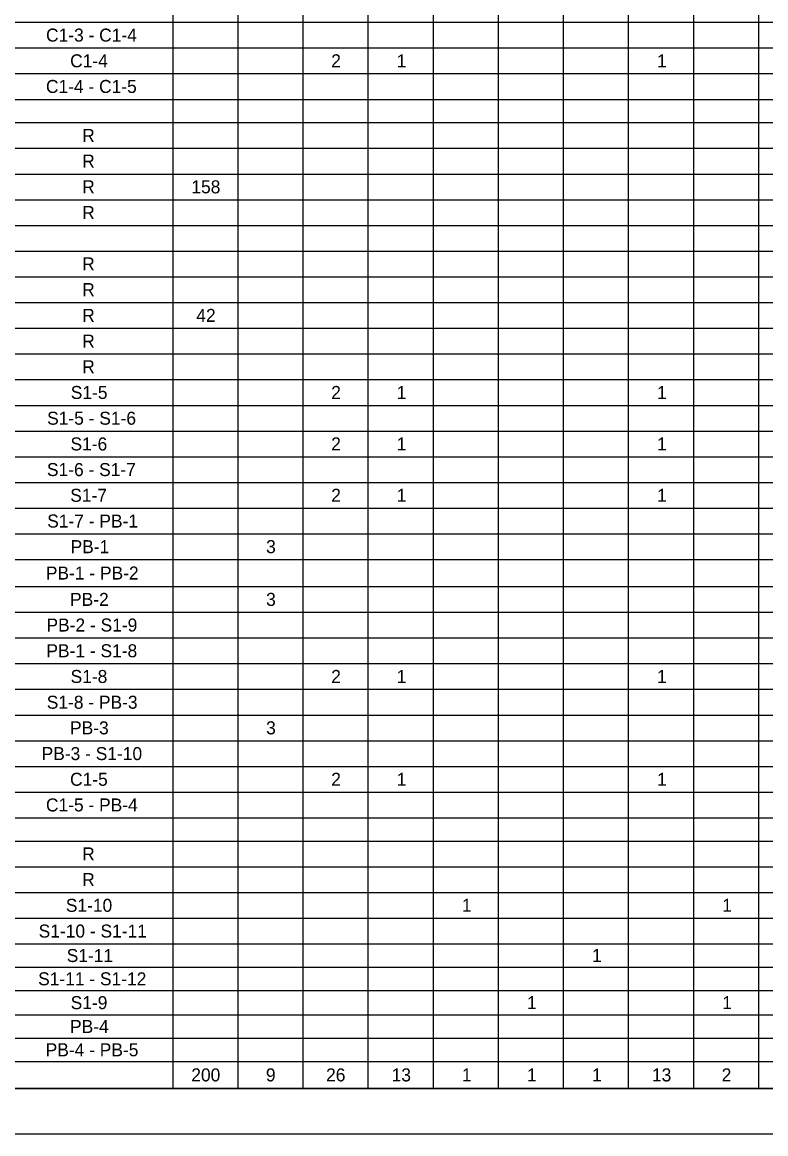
# Model space of a CAD drawing. Extents: x -1022.2 to -988.2, y -965.8 to -943.8.
# Drawn here: x -1013.62 to -1005.35, y -965.79 to -953.43 of the extents above; entities that cross this region are included whole.
import ezdxf

# ---------------------------------------------------------------- set-up
doc = ezdxf.new("R2010")
doc.units = 0
for name, color, linetype in [('Default', 7, 'Continuous'), ('SH_Border', 7, 'Continuous'), ('SH_Cut_Line', 7, 'Continuous')]:
    doc.layers.add(name, color=color, linetype=linetype)

msp = doc.modelspace()

# ---------------------------------------------------------------- linework, layer by layer
at = {"layer": 'Default'}
for p, q in [((-1011.942, -952.573), (-1011.942, -953.43)), ((-1011.218, -952.573), (-1011.218, -953.43)), ((-1010.494, -952.573), (-1010.494, -953.43)), ((-1009.771, -952.573), (-1009.771, -953.43)), ((-1009.047, -952.573), (-1009.047, -953.43)), ((-1008.323, -952.573), (-1008.323, -953.43)), ((-1007.6, -952.573), (-1007.6, -953.43)), ((-1006.876, -952.573), (-1006.876, -953.43)), ((-1006.152, -952.573), (-1006.152, -953.43)), ((-1005.428, -952.573), (-1005.428, -953.43)), ((-1016.817, -953.43), (-1009.047, -953.43)), ((-1011.942, -953.43), (-1011.942, -954.001)), ((-1011.218, -953.43), (-1011.218, -954.001)), ((-1010.494, -953.43), (-1010.494, -954.001)), ((-1009.771, -953.43), (-1009.771, -954.001)), ((-1009.047, -953.43), (-1008.323, -953.43)), ((-1009.047, -953.43), (-1009.047, -954.001)), ((-1008.323, -953.43), (-1007.6, -953.43)), ((-1008.323, -953.43), (-1008.323, -954.001)), ((-1007.6, -953.43), (-1006.876, -953.43)), ((-1007.6, -953.43), (-1007.6, -954.001)), ((-1006.876, -953.43), (-1005.428, -953.43)), ((-1006.876, -953.43), (-1006.876, -954.001)), ((-1006.152, -953.43), (-1006.152, -954.001)), ((-1005.428, -953.43), (-998.915, -953.43)), ((-1005.428, -953.43), (-1005.428, -954.001)), ((-1016.817, -953.716), (-1009.047, -953.716)), ((-1009.047, -953.716), (-1008.323, -953.716)), ((-1008.323, -953.716), (-1007.6, -953.716)), ((-1007.6, -953.716), (-1006.876, -953.716)), ((-1006.876, -953.716), (-1005.428, -953.716)), ((-1005.428, -953.716), (-998.915, -953.716)), ((-1016.817, -954.001), (-1009.047, -954.001)), ((-1011.942, -954.001), (-1011.942, -955.403)), ((-1011.218, -954.001), (-1011.218, -955.403)), ((-1010.494, -954.001), (-1010.494, -955.403)), ((-1009.771, -954.001), (-1009.771, -955.403)), ((-1009.047, -954.001), (-1008.323, -954.001)), ((-1009.047, -954.001), (-1009.047, -955.403)), ((-1008.323, -954.001), (-1007.6, -954.001)), ((-1008.323, -954.001), (-1008.323, -955.403)), ((-1007.6, -954.001), (-1006.876, -954.001)), ((-1007.6, -954.001), (-1007.6, -955.403)), ((-1006.876, -954.001), (-1005.428, -954.001)), ((-1006.876, -954.001), (-1006.876, -955.403)), ((-1006.152, -954.001), (-1006.152, -955.403)), ((-1005.428, -954.001), (-998.915, -954.001)), ((-1005.428, -954.001), (-1005.428, -955.403)), ((-1016.817, -954.287), (-1009.047, -954.287)), ((-1009.047, -954.287), (-1008.323, -954.287)), ((-1008.323, -954.287), (-1007.6, -954.287)), ((-1007.6, -954.287), (-1006.876, -954.287)), ((-1006.876, -954.287), (-1005.428, -954.287)), ((-1005.428, -954.287), (-998.915, -954.287)), ((-1016.817, -954.546), (-1009.047, -954.546)), ((-1009.047, -954.546), (-1008.323, -954.546)), ((-1008.323, -954.546), (-1007.6, -954.546)), ((-1007.6, -954.546), (-1006.876, -954.546)), ((-1006.876, -954.546), (-1005.428, -954.546)), ((-1005.428, -954.546), (-998.915, -954.546)), ((-1016.817, -954.831), (-1009.047, -954.831)), ((-1009.047, -954.831), (-1008.323, -954.831)), ((-1008.323, -954.831), (-1007.6, -954.831)), ((-1007.6, -954.831), (-1006.876, -954.831)), ((-1006.876, -954.831), (-1005.428, -954.831)), ((-1005.428, -954.831), (-998.915, -954.831)), ((-1016.817, -955.117), (-1009.047, -955.117)), ((-1009.047, -955.117), (-1008.323, -955.117)), ((-1008.323, -955.117), (-1007.6, -955.117)), ((-1007.6, -955.117), (-1006.876, -955.117)), ((-1006.876, -955.117), (-1005.428, -955.117)), ((-1005.428, -955.117), (-998.915, -955.117)), ((-1016.817, -955.403), (-1009.047, -955.403)), ((-1011.942, -955.403), (-1011.942, -955.974)), ((-1011.218, -955.403), (-1011.218, -955.974)), ((-1010.494, -955.403), (-1010.494, -955.974)), ((-1009.771, -955.403), (-1009.771, -955.974)), ((-1009.047, -955.403), (-1008.323, -955.403)), ((-1009.047, -955.403), (-1009.047, -955.974)), ((-1008.323, -955.403), (-1007.6, -955.403)), ((-1008.323, -955.403), (-1008.323, -955.974)), ((-1007.6, -955.403), (-1006.876, -955.403)), ((-1007.6, -955.403), (-1007.6, -955.974)), ((-1006.876, -955.403), (-1005.428, -955.403)), ((-1006.876, -955.403), (-1006.876, -955.974)), ((-1006.152, -955.403), (-1006.152, -955.974)), ((-1005.428, -955.403), (-998.915, -955.403)), ((-1005.428, -955.403), (-1005.428, -955.974)), ((-1016.817, -955.688), (-1009.047, -955.688)), ((-1009.047, -955.688), (-1008.323, -955.688)), ((-1008.323, -955.688), (-1007.6, -955.688)), ((-1007.6, -955.688), (-1006.876, -955.688)), ((-1006.876, -955.688), (-1005.428, -955.688)), ((-1005.428, -955.688), (-998.915, -955.688)), ((-1016.817, -955.974), (-1009.047, -955.974)), ((-1011.942, -955.974), (-1011.942, -956.831)), ((-1011.218, -955.974), (-1011.218, -956.831)), ((-1010.494, -955.974), (-1010.494, -956.831)), ((-1009.771, -955.974), (-1009.771, -956.831)), ((-1009.047, -955.974), (-1008.323, -955.974)), ((-1009.047, -955.974), (-1009.047, -956.831)), ((-1008.323, -955.974), (-1007.6, -955.974)), ((-1008.323, -955.974), (-1008.323, -956.831)), ((-1007.6, -955.974), (-1006.876, -955.974)), ((-1007.6, -955.974), (-1007.6, -956.831)), ((-1006.876, -955.974), (-1005.428, -955.974)), ((-1006.876, -955.974), (-1006.876, -956.831)), ((-1006.152, -955.974), (-1006.152, -956.831)), ((-1005.428, -955.974), (-998.915, -955.974)), ((-1005.428, -955.974), (-1005.428, -956.831)), ((-1016.817, -956.26), (-1009.047, -956.26)), ((-1009.047, -956.26), (-1008.323, -956.26)), ((-1008.323, -956.26), (-1007.6, -956.26)), ((-1007.6, -956.26), (-1006.876, -956.26)), ((-1006.876, -956.26), (-1005.428, -956.26)), ((-1005.428, -956.26), (-998.915, -956.26)), ((-1016.817, -956.546), (-1009.047, -956.546)), ((-1009.047, -956.546), (-1008.323, -956.546)), ((-1008.323, -956.546), (-1007.6, -956.546)), ((-1007.6, -956.546), (-1006.876, -956.546)), ((-1006.876, -956.546), (-1005.428, -956.546)), ((-1005.428, -956.546), (-998.915, -956.546)), ((-1016.817, -956.831), (-1009.047, -956.831)), ((-1011.942, -956.831), (-1011.942, -957.403)), ((-1011.218, -956.831), (-1011.218, -957.403)), ((-1010.494, -956.831), (-1010.494, -957.403)), ((-1009.771, -956.831), (-1009.771, -957.403)), ((-1009.047, -956.831), (-1008.323, -956.831)), ((-1009.047, -956.831), (-1009.047, -957.403)), ((-1008.323, -956.831), (-1007.6, -956.831)), ((-1008.323, -956.831), (-1008.323, -957.403)), ((-1007.6, -956.831), (-1006.876, -956.831)), ((-1007.6, -956.831), (-1007.6, -957.403)), ((-1006.876, -956.831), (-1005.428, -956.831)), ((-1006.876, -956.831), (-1006.876, -957.403)), ((-1006.152, -956.831), (-1006.152, -957.403)), ((-1005.428, -956.831), (-998.915, -956.831)), ((-1005.428, -956.831), (-1005.428, -957.403)), ((-1016.817, -957.117), (-1009.047, -957.117)), ((-1009.047, -957.117), (-1008.323, -957.117)), ((-1008.323, -957.117), (-1007.6, -957.117)), ((-1007.6, -957.117), (-1006.876, -957.117)), ((-1006.876, -957.117), (-1005.428, -957.117)), ((-1005.428, -957.117), (-998.915, -957.117)), ((-1016.817, -957.403), (-1009.047, -957.403)), ((-1011.942, -957.403), (-1011.942, -958.26)), ((-1011.218, -957.403), (-1011.218, -958.26)), ((-1010.494, -957.403), (-1010.494, -958.26)), ((-1009.771, -957.403), (-1009.771, -958.26)), ((-1009.047, -957.403), (-1008.323, -957.403)), ((-1009.047, -957.403), (-1009.047, -958.26)), ((-1008.323, -957.403), (-1007.6, -957.403)), ((-1008.323, -957.403), (-1008.323, -958.26)), ((-1007.6, -957.403), (-1006.876, -957.403)), ((-1007.6, -957.403), (-1007.6, -958.26)), ((-1006.876, -957.403), (-1005.428, -957.403)), ((-1006.876, -957.403), (-1006.876, -958.26)), ((-1006.152, -957.403), (-1006.152, -958.26)), ((-1005.428, -957.403), (-998.915, -957.403)), ((-1005.428, -957.403), (-1005.428, -958.26)), ((-1016.817, -957.689), (-1009.047, -957.689)), ((-1009.047, -957.689), (-1008.323, -957.689)), ((-1008.323, -957.689), (-1007.6, -957.689)), ((-1007.6, -957.689), (-1006.876, -957.689)), ((-1006.876, -957.689), (-1005.428, -957.689)), ((-1005.428, -957.689), (-998.915, -957.689)), ((-1016.817, -957.974), (-1009.047, -957.974)), ((-1009.047, -957.974), (-1008.323, -957.974)), ((-1008.323, -957.974), (-1007.6, -957.974)), ((-1007.6, -957.974), (-1006.876, -957.974)), ((-1006.876, -957.974), (-1005.428, -957.974)), ((-1005.428, -957.974), (-998.915, -957.974)), ((-1016.817, -958.26), (-1009.047, -958.26)), ((-1011.942, -958.26), (-1011.942, -958.832)), ((-1011.218, -958.26), (-1011.218, -958.832)), ((-1010.494, -958.26), (-1010.494, -958.832)), ((-1009.771, -958.26), (-1009.771, -958.832)), ((-1009.047, -958.26), (-1008.323, -958.26)), ((-1009.047, -958.26), (-1009.047, -958.832)), ((-1008.323, -958.26), (-1007.6, -958.26)), ((-1008.323, -958.26), (-1008.323, -958.832)), ((-1007.6, -958.26), (-1006.876, -958.26)), ((-1007.6, -958.26), (-1007.6, -958.832)), ((-1006.876, -958.26), (-1005.428, -958.26)), ((-1006.876, -958.26), (-1006.876, -958.832)), ((-1006.152, -958.26), (-1006.152, -958.832)), ((-1005.428, -958.26), (-998.915, -958.26)), ((-1005.428, -958.26), (-1005.428, -958.832)), ((-1016.817, -958.546), (-1009.047, -958.546)), ((-1009.047, -958.546), (-1008.323, -958.546)), ((-1008.323, -958.546), (-1007.6, -958.546)), ((-1007.6, -958.546), (-1006.876, -958.546)), ((-1006.876, -958.546), (-1005.428, -958.546)), ((-1005.428, -958.546), (-998.915, -958.546)), ((-1016.817, -958.832), (-1009.047, -958.832)), ((-1011.942, -958.832), (-1011.942, -959.702)), ((-1011.218, -958.832), (-1011.218, -959.702)), ((-1010.494, -958.832), (-1010.494, -959.702)), ((-1009.771, -958.832), (-1009.771, -959.702)), ((-1009.047, -958.832), (-1008.323, -958.832)), ((-1009.047, -958.832), (-1009.047, -959.702)), ((-1008.323, -958.832), (-1007.6, -958.832)), ((-1008.323, -958.832), (-1008.323, -959.702)), ((-1007.6, -958.832), (-1006.876, -958.832)), ((-1007.6, -958.832), (-1007.6, -959.702)), ((-1006.876, -958.832), (-1005.428, -958.832)), ((-1006.876, -958.832), (-1006.876, -959.702)), ((-1006.152, -958.832), (-1006.152, -959.702)), ((-1005.428, -958.832), (-998.915, -958.832)), ((-1005.428, -958.832), (-1005.428, -959.702)), ((-1016.817, -959.117), (-1009.047, -959.117)), ((-1009.047, -959.117), (-1008.323, -959.117)), ((-1008.323, -959.117), (-1007.6, -959.117)), ((-1007.6, -959.117), (-1006.876, -959.117)), ((-1006.876, -959.117), (-1005.428, -959.117)), ((-1005.428, -959.117), (-998.915, -959.117)), ((-1016.817, -959.403), (-1009.047, -959.403)), ((-1009.047, -959.403), (-1008.323, -959.403)), ((-1008.323, -959.403), (-1007.6, -959.403)), ((-1007.6, -959.403), (-1006.876, -959.403)), ((-1006.876, -959.403), (-1005.428, -959.403)), ((-1005.428, -959.403), (-998.915, -959.403)), ((-1016.817, -959.702), (-1009.047, -959.702)), ((-1011.942, -959.702), (-1011.942, -959.988)), ((-1011.218, -959.702), (-1011.218, -959.988)), ((-1010.494, -959.702), (-1010.494, -959.988)), ((-1009.771, -959.702), (-1009.771, -959.988)), ((-1009.047, -959.702), (-1008.323, -959.702)), ((-1009.047, -959.702), (-1009.047, -959.988)), ((-1008.323, -959.702), (-1007.6, -959.702)), ((-1008.323, -959.702), (-1008.323, -959.988)), ((-1007.6, -959.702), (-1006.876, -959.702)), ((-1007.6, -959.702), (-1007.6, -959.988)), ((-1006.876, -959.702), (-1005.428, -959.702)), ((-1006.876, -959.702), (-1006.876, -959.988)), ((-1006.152, -959.702), (-1006.152, -959.988)), ((-1005.428, -959.702), (-998.915, -959.702)), ((-1005.428, -959.702), (-1005.428, -959.988)), ((-1016.817, -959.988), (-1009.047, -959.988)), ((-1011.942, -959.988), (-1011.942, -965.281)), ((-1011.218, -959.988), (-1011.218, -965.281)), ((-1010.494, -959.988), (-1010.494, -965.281)), ((-1009.771, -959.988), (-1009.771, -965.281)), ((-1009.047, -959.988), (-1008.323, -959.988)), ((-1009.047, -959.988), (-1009.047, -965.281)), ((-1008.323, -959.988), (-1007.6, -959.988)), ((-1008.323, -959.988), (-1008.323, -965.281)), ((-1007.6, -959.988), (-1006.876, -959.988)), ((-1007.6, -959.988), (-1007.6, -965.281)), ((-1006.876, -959.988), (-1005.428, -959.988)), ((-1006.876, -959.988), (-1006.876, -965.281)), ((-1006.152, -959.988), (-1006.152, -965.281)), ((-1005.428, -959.988), (-998.915, -959.988)), ((-1005.428, -959.988), (-1005.428, -965.281)), ((-1016.817, -960.274), (-1009.047, -960.274)), ((-1009.047, -960.274), (-1008.323, -960.274)), ((-1008.323, -960.274), (-1007.6, -960.274)), ((-1007.6, -960.274), (-1006.876, -960.274)), ((-1006.876, -960.274), (-1005.428, -960.274)), ((-1005.428, -960.274), (-998.915, -960.274)), ((-1016.817, -960.56), (-1009.047, -960.56)), ((-1009.047, -960.56), (-1008.323, -960.56)), ((-1008.323, -960.56), (-1007.6, -960.56)), ((-1007.6, -960.56), (-1006.876, -960.56)), ((-1006.876, -960.56), (-1005.428, -960.56)), ((-1005.428, -960.56), (-998.915, -960.56)), ((-1016.817, -960.845), (-1009.047, -960.845)), ((-1009.047, -960.845), (-1008.323, -960.845)), ((-1008.323, -960.845), (-1007.6, -960.845)), ((-1007.6, -960.845), (-1006.876, -960.845)), ((-1006.876, -960.845), (-1005.428, -960.845)), ((-1005.428, -960.845), (-998.915, -960.845)), ((-1016.817, -961.131), (-1009.047, -961.131)), ((-1009.047, -961.131), (-1008.323, -961.131)), ((-1008.323, -961.131), (-1007.6, -961.131)), ((-1007.6, -961.131), (-1006.876, -961.131)), ((-1006.876, -961.131), (-1005.428, -961.131)), ((-1005.428, -961.131), (-998.915, -961.131)), ((-1016.817, -961.417), (-1009.047, -961.417)), ((-1009.047, -961.417), (-1008.323, -961.417)), ((-1008.323, -961.417), (-1007.6, -961.417)), ((-1007.6, -961.417), (-1006.876, -961.417)), ((-1006.876, -961.417), (-1005.428, -961.417)), ((-1005.428, -961.417), (-998.915, -961.417)), ((-1016.817, -961.703), (-1009.047, -961.703)), ((-1009.047, -961.703), (-1008.323, -961.703)), ((-1008.323, -961.703), (-1007.6, -961.703)), ((-1007.6, -961.703), (-1006.876, -961.703)), ((-1006.876, -961.703), (-1005.428, -961.703)), ((-1005.428, -961.703), (-998.915, -961.703)), ((-1016.817, -961.988), (-1009.047, -961.988)), ((-1009.047, -961.988), (-1008.323, -961.988)), ((-1008.323, -961.988), (-1007.6, -961.988)), ((-1007.6, -961.988), (-1006.876, -961.988)), ((-1006.876, -961.988), (-1005.428, -961.988)), ((-1005.428, -961.988), (-998.915, -961.988)), ((-1016.817, -962.274), (-1009.047, -962.274)), ((-1009.047, -962.274), (-1008.323, -962.274)), ((-1008.323, -962.274), (-1007.6, -962.274)), ((-1007.6, -962.274), (-1006.876, -962.274)), ((-1006.876, -962.274), (-1005.428, -962.274)), ((-1005.428, -962.274), (-998.915, -962.274)), ((-1016.817, -962.533), (-1009.047, -962.533)), ((-1009.047, -962.533), (-1008.323, -962.533)), ((-1008.323, -962.533), (-1007.6, -962.533)), ((-1007.6, -962.533), (-1006.876, -962.533)), ((-1006.876, -962.533), (-1005.428, -962.533)), ((-1005.428, -962.533), (-998.915, -962.533)), ((-1016.817, -962.818), (-1009.047, -962.818)), ((-1009.047, -962.818), (-1008.323, -962.818)), ((-1008.323, -962.818), (-1007.6, -962.818)), ((-1007.6, -962.818), (-1006.876, -962.818)), ((-1006.876, -962.818), (-1005.428, -962.818)), ((-1005.428, -962.818), (-998.915, -962.818)), ((-1016.817, -963.104), (-1009.047, -963.104)), ((-1009.047, -963.104), (-1008.323, -963.104)), ((-1008.323, -963.104), (-1007.6, -963.104)), ((-1007.6, -963.104), (-1006.876, -963.104)), ((-1006.876, -963.104), (-1005.428, -963.104)), ((-1005.428, -963.104), (-998.915, -963.104)), ((-1016.817, -963.39), (-1009.047, -963.39)), ((-1009.047, -963.39), (-1008.323, -963.39)), ((-1008.323, -963.39), (-1007.6, -963.39)), ((-1007.6, -963.39), (-1006.876, -963.39)), ((-1006.876, -963.39), (-1005.428, -963.39)), ((-1005.428, -963.39), (-998.915, -963.39)), ((-1016.817, -963.676), (-1009.047, -963.676)), ((-1009.047, -963.676), (-1008.323, -963.676)), ((-1008.323, -963.676), (-1007.6, -963.676)), ((-1007.6, -963.676), (-1006.876, -963.676)), ((-1006.876, -963.676), (-1005.428, -963.676)), ((-1005.428, -963.676), (-998.915, -963.676)), ((-1016.817, -963.934), (-1009.047, -963.934)), ((-1009.047, -963.934), (-1008.323, -963.934)), ((-1008.323, -963.934), (-1007.6, -963.934)), ((-1007.6, -963.934), (-1006.876, -963.934)), ((-1006.876, -963.934), (-1005.428, -963.934)), ((-1005.428, -963.934), (-998.915, -963.934)), ((-1016.817, -964.193), (-1009.047, -964.193)), ((-1009.047, -964.193), (-1008.323, -964.193)), ((-1008.323, -964.193), (-1007.6, -964.193)), ((-1007.6, -964.193), (-1006.876, -964.193)), ((-1006.876, -964.193), (-1005.428, -964.193)), ((-1005.428, -964.193), (-998.915, -964.193)), ((-1016.817, -964.465), (-1009.047, -964.465)), ((-1009.047, -964.465), (-1008.323, -964.465)), ((-1008.323, -964.465), (-1007.6, -964.465)), ((-1007.6, -964.465), (-1006.876, -964.465)), ((-1006.876, -964.465), (-1005.428, -964.465)), ((-1005.428, -964.465), (-998.915, -964.465)), ((-1016.817, -964.723), (-1009.047, -964.723)), ((-1009.047, -964.723), (-1008.323, -964.723)), ((-1008.323, -964.723), (-1007.6, -964.723)), ((-1007.6, -964.723), (-1006.876, -964.723)), ((-1006.876, -964.723), (-1005.428, -964.723)), ((-1005.428, -964.723), (-998.915, -964.723)), ((-1016.817, -964.982), (-1009.047, -964.982)), ((-1009.047, -964.982), (-1008.323, -964.982)), ((-1008.323, -964.982), (-1007.6, -964.982)), ((-1007.6, -964.982), (-1006.876, -964.982)), ((-1006.876, -964.982), (-1005.428, -964.982)), ((-1005.428, -964.982), (-998.915, -964.982)), ((-1016.817, -965.281), (-1009.047, -965.281)), ((-1009.047, -965.281), (-1008.323, -965.281)), ((-1008.323, -965.281), (-1007.6, -965.281)), ((-1007.6, -965.281), (-1006.876, -965.281)), ((-1006.876, -965.281), (-1005.428, -965.281)), ((-1005.428, -965.281), (-998.915, -965.281))]:
    msp.add_line(p, q, dxfattribs=at)
at = {"layer": 'SH_Border'}
msp.add_lwpolyline([(-1020.749, -944.286), (-988.749, -944.286), (-988.749, -965.286), (-1020.749, -965.286)], close=True, dxfattribs=at)
at = {"layer": 'SH_Cut_Line'}
msp.add_lwpolyline([(-1022.249, -965.786), (-988.249, -965.786), (-988.249, -943.786), (-1022.249, -943.786)], close=True, dxfattribs=at)

# ---------------------------------------------------------------- texts
at = {"layer": 'Default'}
for s, height, p in [('C1-3 - C1-4', 0.14457, (-1013.351, -953.645)), ('C1-4', 0.1446, (-1013.083, -953.931)), ('2', 0.145, (-1010.18, -953.931)), ('1', 0.145, (-1009.451, -953.931)), ('1', 0.145, (-1006.556, -953.931)), ('C1-4 - C1-5', 0.14457, (-1013.352, -954.216)), ('R', 0.145, (-1012.949, -954.761)), ('R', 0.145, (-1012.949, -955.046)), ('R', 0.145, (-1012.949, -955.332)), ('158', 0.1446, (-1011.735, -955.332)), ('R', 0.145, (-1012.949, -955.618)), ('R', 0.145, (-1012.949, -956.189)), ('R', 0.145, (-1012.949, -956.475)), ('R', 0.145, (-1012.949, -956.761)), ('42', 0.1446, (-1011.68, -956.761)), ('R', 0.145, (-1012.949, -957.047)), ('R', 0.145, (-1012.949, -957.332)), ('S1-5', 0.1446, (-1013.076, -957.618)), ('2', 0.145, (-1010.18, -957.618)), ('1', 0.145, (-1009.451, -957.618)), ('1', 0.145, (-1006.556, -957.618)), ('S1-5 - S1-6', 0.14457, (-1013.339, -957.904)), ('S1-6', 0.1446, (-1013.079, -958.19)), ('2', 0.145, (-1010.18, -958.19)), ('1', 0.145, (-1009.451, -958.19)), ('1', 0.145, (-1006.556, -958.19)), ('S1-6 - S1-7', 0.14457, (-1013.341, -958.475)), ('S1-7', 0.1446, (-1013.082, -958.761)), ('2', 0.145, (-1010.18, -958.761)), ('1', 0.145, (-1009.451, -958.761)), ('1', 0.145, (-1006.556, -958.761)), ('S1-7 - PB-1', 0.14457, (-1013.338, -959.047)), ('PB-1', 0.1446, (-1013.078, -959.332)), ('3', 0.145, (-1010.904, -959.332)), ('PB-1 - PB-2', 0.14457, (-1013.353, -959.625)), ('PB-2', 0.1446, (-1013.084, -959.918)), ('3', 0.145, (-1010.904, -959.918)), ('PB-2 - S1-9', 0.14457, (-1013.346, -960.203)), ('PB-1 - S1-8', 0.14457, (-1013.347, -960.489)), ('S1-8', 0.1446, (-1013.078, -960.775)), ('2', 0.145, (-1010.18, -960.775)), ('1', 0.145, (-1009.451, -960.775)), ('1', 0.145, (-1006.556, -960.775)), ('S1-8 - PB-3', 0.14457, (-1013.343, -961.061)), ('PB-3', 0.1446, (-1013.084, -961.346)), ('3', 0.145, (-1010.904, -961.346)), ('PB-3 - S1-10', 0.14457, (-1013.4, -961.632)), ('C1-5', 0.1446, (-1013.084, -961.918)), ('2', 0.145, (-1010.18, -961.918)), ('1', 0.145, (-1009.451, -961.918)), ('1', 0.145, (-1006.556, -961.918)), ('C1-5 - PB-4', 0.14457, (-1013.352, -962.203)), ('R', 0.145, (-1012.949, -962.748)), ('R', 0.145, (-1012.949, -963.033)), ('S1-10', 0.1446, (-1013.131, -963.319)), ('1', 0.145, (-1008.727, -963.319)), ('1', 0.145, (-1005.832, -963.319)), ('S1-10 - S1-11', 0.14457, (-1013.433, -963.605)), ('S1-11', 0.1446, (-1013.121, -963.877)), ('1', 0.145, (-1007.28, -963.877)), ('S1-11 - S1-12', 0.14457, (-1013.439, -964.136)), ('S1-9', 0.1446, (-1013.077, -964.401)), ('1', 0.145, (-1008.003, -964.401)), ('1', 0.145, (-1005.832, -964.401)), ('PB-4', 0.1446, (-1013.084, -964.666)), ('PB-4 - PB-5', 0.14457, (-1013.355, -964.925)), ('200', 0.1446, (-1011.736, -965.204)), ('9', 0.145, (-1010.906, -965.204)), ('26', 0.1446, (-1010.237, -965.204)), ('13', 0.1446, (-1009.508, -965.204)), ('1', 0.145, (-1008.727, -965.204)), ('1', 0.145, (-1008.003, -965.204)), ('1', 0.145, (-1007.28, -965.204)), ('13', 0.1446, (-1006.613, -965.204)), ('2', 0.145, (-1005.838, -965.204))]:
    msp.add_text(s, height=height, dxfattribs=at).set_placement(p)

doc.saveas('drawing.dxf')
